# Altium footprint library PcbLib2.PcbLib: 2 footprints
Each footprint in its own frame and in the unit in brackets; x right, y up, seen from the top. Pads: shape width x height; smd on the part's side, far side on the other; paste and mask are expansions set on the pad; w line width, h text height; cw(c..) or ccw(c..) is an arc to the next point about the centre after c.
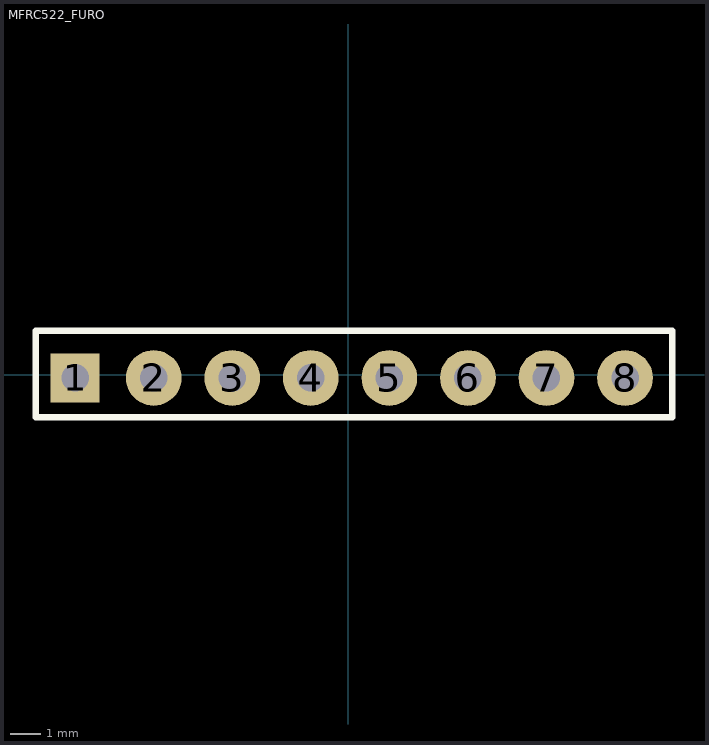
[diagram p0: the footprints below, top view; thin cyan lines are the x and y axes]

## MFRC522_FURO [mm]
pads (8):
  rect 1.575x1.575 hole 0.889: 1(-8.832,-0.099)
  round 1.8 hole 0.889: 2(-6.292,-0.099) 3(-3.752,-0.099) 4(-1.212,-0.099) 5(1.328,-0.099) 6(3.868,-0.099) 7(6.408,-0.099) 8(8.948,-0.099)
Top Overlay:
  lines w0.203: -10.102,-1.369 -10.102,1.425 10.472,1.425 10.472,-1.369 -10.102,-1.369

## PCBComponent_1 [mm]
